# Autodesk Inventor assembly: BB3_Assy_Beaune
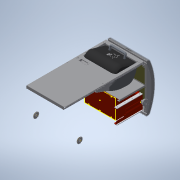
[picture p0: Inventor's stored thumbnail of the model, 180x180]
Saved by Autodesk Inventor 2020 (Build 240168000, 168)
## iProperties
Created: 2008-11
Part Number: BB3_Assy_Beaune
Document SubType Name: Assembly
Designer: claivier
Author: claivier
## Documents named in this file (11)
- D:\Cours\1-Cours-2020-21\1-Site\Elèves\TSTI2D\Tronc-commun\EDC-RDM-Big-Belly\lib\Big-Belly\Big-Belly\BB3_Assy_Beaune.iam
- D:\Cours\1-Cours-2020-21\1-Site\Elèves\TSTI2D\Tronc-commun\EDC-RDM-Big-Belly\lib\Big-Belly\Big-Belly\BB3_Chassis.iam
- D:\Cours\1-Cours-2020-21\1-Site\Elèves\TSTI2D\Tronc-commun\EDC-RDM-Big-Belly\lib\Big-Belly\Big-Belly\BB3_Axe_Moteur.iam
- D:\Cours\1-Cours-2020-21\1-Site\Elèves\TSTI2D\Tronc-commun\EDC-RDM-Big-Belly\lib\Big-Belly\Big-Belly\BB3_Pignon_Bas.iam
- D:\Cours\1-Cours-2020-21\1-Site\Elèves\TSTI2D\Tronc-commun\EDC-RDM-Big-Belly\lib\Big-Belly\Big-Belly\BB3_Coulissant_Vertical.iam
- D:\Cours\1-Cours-2020-21\1-Site\Elèves\TSTI2D\Tronc-commun\EDC-RDM-Big-Belly\lib\Big-Belly\Big-Belly\BB3_Porte.iam
- D:\Cours\1-Cours-2020-21\1-Site\Elèves\TSTI2D\Tronc-commun\EDC-RDM-Big-Belly\lib\Big-Belly\Big-Belly\BB3_Dévidoir.iam
- D:\Cours\1-Cours-2020-21\1-Site\Elèves\TSTI2D\Tronc-commun\EDC-RDM-Big-Belly\lib\Big-Belly\Big-Belly\BB3_Protection_Avant.iam
- D:\Cours\1-Cours-2020-21\1-Site\Elèves\TSTI2D\Tronc-commun\EDC-RDM-Big-Belly\lib\Big-Belly\Big-Belly\BB3_Panneau_Solaire.iam
- D:\Cours\1-Cours-2020-21\1-Site\Elèves\TSTI2D\Tronc-commun\EDC-RDM-Big-Belly\lib\Big-Belly\Big-Belly\BB3_Rame_Compacteur_2.iam
- D:\Cours\1-Cours-2020-21\1-Site\Elèves\TSTI2D\Tronc-commun\EDC-RDM-Big-Belly\lib\Big-Belly\Big-Belly\BB3_Coulissant_Vertical_Crémaillère.ipt
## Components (14 placed, 10 different names)
1. BB3_Chassis:1 [sub-assembly] — Affleurement:1, Plaquage:2, Affleurement:3, Affleurement:4, Plaquage:6, Affleurement:8, Affleurement:9, Plaquage:9, Plaquage:8, Angle:3, Plaquage:11, Plaquage:12, Angle:5, Affleurement:10, Plaquage:13, Plaquage:14, Angle:6, Plaquage:3, Plaquage:1
2. BB3_Axe_Moteur:1 [sub-assembly] — Affleurement:1, Angle:1, Angle:2, Rotation/Translation:1, Affleurement:6, Affleurement:2, Affleurement:11, Tangente:1, Affleurement:13, Tangente:3, Plaquage:1
3. BB3_Pignon_Bas:1 [sub-assembly] — Plaquage:2, Angle:1, Affleurement:2, Affleurement:14, Tangente:4
4. BB3_Rame_Compacteur_2:1 [sub-assembly] — Affleurement:3, Affleurement:4, Plaquage:4, Plaquage:5, Rotation/Translation:1, Plaquage:3, Plaquage:10, Plaquage:16, Plaquage:17, Plaquage:19, Plaquage:18
5. BB3_Coulissant_Vertical:1 [sub-assembly] — Plaquage:4, Plaquage:5, Plaquage:10
6. BB3_Pignon_Bas:2 [sub-assembly] — Plaquage:6, Angle:2, Affleurement:6, Affleurement:12, Tangente:2
7. BB3_Porte:1 [sub-assembly] — Plaquage:9, Plaquage:8, Affleurement:7, Plaquage:7, Angle:4, Angle:3, Angle:7
8. BB3_Dévidoir:1 [sub-assembly] — Affleurement:7, Plaquage:7, Angle:4, Angle:7
9. BB3_Protection_Avant:1 [sub-assembly] — Plaquage:11, Plaquage:12, Angle:5
10. BB3_Panneau_Solaire:1 [sub-assembly] — Plaquage:13, Plaquage:14, Angle:6
11. BB3_Coulissant_Vertical_Crémaillère:1 — Plaquage:16, Affleurement:11, Tangente:1
12. BB3_Coulissant_Vertical_Crémaillère:2 — Plaquage:17, Affleurement:12, Tangente:2
13. BB3_Coulissant_Vertical_Crémaillère:3 — Affleurement:13, Tangente:3, Plaquage:18
14. BB3_Coulissant_Vertical_Crémaillère:4 — Affleurement:14, Tangente:4, Plaquage:19
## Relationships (43: Mate 18, Flush 13, Angle 7, Tangent 4, RelateRotateTranslate 1)
- Affleurement:1 [Flush]: BB3_Chassis:1 ↔ BB3_Axe_Moteur:1
- Plaquage:2 [Mate]: BB3_Chassis:1 ↔ BB3_Pignon_Bas:1
- Affleurement:3 [Flush]: BB3_Chassis:1 ↔ BB3_Rame_Compacteur_2:1
- Affleurement:4 [Flush]: BB3_Chassis:1 ↔ BB3_Rame_Compacteur_2:1
- Angle:1: BB3_Axe_Moteur:1 ↔ BB3_Pignon_Bas:1
- Plaquage:4 [Mate]: BB3_Rame_Compacteur_2:1 ↔ BB3_Coulissant_Vertical:1
- Plaquage:5 [Mate]: BB3_Rame_Compacteur_2:1 ↔ BB3_Coulissant_Vertical:1
- Plaquage:6 [Mate]: BB3_Chassis:1 ↔ BB3_Pignon_Bas:2
- Angle:2: BB3_Axe_Moteur:1 ↔ BB3_Pignon_Bas:2
- Rotation/Translation:1 [RelateRotateTranslate]: BB3_Axe_Moteur:1 ↔ BB3_Rame_Compacteur_2:1
- Affleurement:8 [Flush]: BB3_Chassis:1
- Affleurement:9 [Flush]: BB3_Chassis:1
- Plaquage:9 [Mate]: BB3_Chassis:1 ↔ BB3_Porte:1
- Plaquage:8 [Mate]: BB3_Chassis:1 ↔ BB3_Porte:1
- Affleurement:7 [Flush]: BB3_Porte:1 ↔ BB3_Dévidoir:1
- Plaquage:7 [Mate]: BB3_Porte:1 ↔ BB3_Dévidoir:1
- Angle:4: BB3_Porte:1 ↔ BB3_Dévidoir:1
- Angle:3: BB3_Chassis:1 ↔ BB3_Porte:1
- Plaquage:11 [Mate]: BB3_Chassis:1 ↔ BB3_Protection_Avant:1
- Plaquage:12 [Mate]: BB3_Chassis:1 ↔ BB3_Protection_Avant:1
- Angle:5: BB3_Chassis:1 ↔ BB3_Protection_Avant:1
- Affleurement:10 [Flush]: BB3_Chassis:1
- Plaquage:13 [Mate]: BB3_Chassis:1 ↔ BB3_Panneau_Solaire:1
- Plaquage:14 [Mate]: BB3_Chassis:1 ↔ BB3_Panneau_Solaire:1
- Angle:6: BB3_Chassis:1 ↔ BB3_Panneau_Solaire:1
- Plaquage:3 [Mate]: BB3_Chassis:1 ↔ BB3_Rame_Compacteur_2:1
- Affleurement:6 [Flush]: BB3_Axe_Moteur:1 ↔ BB3_Pignon_Bas:2
- Affleurement:2 [Flush]: BB3_Axe_Moteur:1 ↔ BB3_Pignon_Bas:1
- Plaquage:10 [Mate]: BB3_Rame_Compacteur_2:1 ↔ BB3_Coulissant_Vertical:1
- Angle:7: BB3_Porte:1 ↔ BB3_Dévidoir:1
- Plaquage:16 [Mate]: BB3_Rame_Compacteur_2:1 ↔ BB3_Coulissant_Vertical_Crémaillère:1
- Affleurement:11 [Flush]: BB3_Axe_Moteur:1 ↔ BB3_Coulissant_Vertical_Crémaillère:1
- Tangente:1: BB3_Axe_Moteur:1 ↔ BB3_Coulissant_Vertical_Crémaillère:1
- Plaquage:17 [Mate]: BB3_Rame_Compacteur_2:1 ↔ BB3_Coulissant_Vertical_Crémaillère:2
- Affleurement:12 [Flush]: BB3_Pignon_Bas:2 ↔ BB3_Coulissant_Vertical_Crémaillère:2
- Tangente:2: BB3_Pignon_Bas:2 ↔ BB3_Coulissant_Vertical_Crémaillère:2
- Affleurement:13 [Flush]: BB3_Axe_Moteur:1 ↔ BB3_Coulissant_Vertical_Crémaillère:3
- Tangente:3: BB3_Axe_Moteur:1 ↔ BB3_Coulissant_Vertical_Crémaillère:3
- Affleurement:14 [Flush]: BB3_Pignon_Bas:1 ↔ BB3_Coulissant_Vertical_Crémaillère:4
- Tangente:4: BB3_Pignon_Bas:1 ↔ BB3_Coulissant_Vertical_Crémaillère:4
- Plaquage:19 [Mate]: BB3_Rame_Compacteur_2:1 ↔ BB3_Coulissant_Vertical_Crémaillère:4
- Plaquage:18 [Mate]: BB3_Rame_Compacteur_2:1 ↔ BB3_Coulissant_Vertical_Crémaillère:3
- Plaquage:1 [Mate]: BB3_Chassis:1 ↔ BB3_Axe_Moteur:1
